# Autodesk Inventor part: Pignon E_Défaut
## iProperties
Shininess: 64.0
Length Units: 11269
Angle Units: 11279
Time Units: 11290
Mass Units: 11283
Length Display Precision: 3
Angle Display Precision: 2
Compacted: True
Part Number: Pignon E_Défaut
Document SubType Name: Modeling
Created: 2006-01
Material: Par défaut
Designer: Fricot
Density: 0.0
Volumn: 0.0
Area: 0.0
PropertySet Name: Model Information
Control State: 0
Master: False
Checked Out: False
Author: Fricot
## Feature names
1. Base1
